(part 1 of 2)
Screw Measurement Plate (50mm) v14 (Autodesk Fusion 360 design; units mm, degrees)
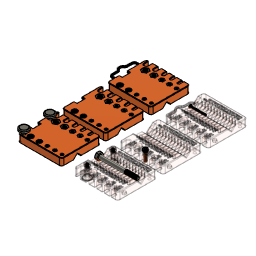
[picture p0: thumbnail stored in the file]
parameter "lengthMeasureLine" = 54 (= "( ( countMeasureCopies * 4 ) * 1 mm ) + 2 mm + 4 mm") comment "Length of measurement line"
parameter "wallMargin" = 0.2 comment "Margin for wall expansion on critical diameters"
sketch "Outline" plane through (0, 0, 0) normal (0, 0, 1) x axis (1, 0, 0)
  line L1 (-27, 10) -> (-31, 10)
  line L2 (-27, 0) -> (-27, 10)
  line L3 (-31, 0) -> (-27, 0)
  line L4 (-31, 10) -> (-31, 0)
  line L5 (27, 5) -> (-27, 5)
  line L6 (0, 5) -> (0, 0)
  line L7 (-31, -8) -> (-31, 0)
  line L8 (-27, -8) -> (-31, -8)
  line L9 (-27, 0) -> (-27, -8)
  line L10 (-27, 18) -> (-27, 10)
  line L11 (-31, 18) -> (-27, 18)
  line L12 (-31, 10) -> (-31, 18)
  line L13 (-31, 26) -> (-31, 18)
  line L14 (27, 26) -> (-31, 26)
  line L15 (27, -26) -> (27, 26)
  line L16 (-31, -26) -> (-31, -8)
  line L17 (27, -26) -> (-31, -26)
  line L18 (27, 0) -> (0, 0)
  line L19 (27, 0) -> (-27, 0)
  line L20 (27, 10) -> (-27, 10)
  point P4 (-27, 0)
  point P6 (-27, 0)
  point P7 (-27, 5)
  point P1 (0, 0)
  point P9 (0, 0)
  point P10 (0, 5)
  point P8 (27, 5)
  point P17 (27, -26)
  point P19 (27, -26)
  point P20 (0, 0)
  point P21 (27, 0)
  point P22 (27, 10)
  point P2 (-31, 10)
  point P5 (-31, 0)
  point P3 (-27, 10)
  point P14 (-31, 18)
  point P15 (-31, 26)
  point P11 (-31, -8)
  point P18 (-31, -26)
  point P16 (27, 26)
  horizontal L1
  vertical L2
  horizontal L3
  vertical L4
  coincident P4 P6
  midpoint L2 P7
  coincident P1 P9
  coincident L5 P10
  vertical L6
  horizontal L5
  midpoint L5 P10
  vertical L12
  horizontal L11
  vertical L10
  vertical L7
  vertical L9
  horizontal L8
  vertical L13
  horizontal L14
  vertical L15
  coincident P8 L15
  perpendicular L8 L16
  coincident P17 P19
  horizontal L17
  coincident P1 P20
  coincident L15 P21
  perpendicular L15 L18
  midpoint L15 P21
  coincident L15 P22
  perpendicular L15 L20
  equal L7 L12
  dimension "d142" distance P2 P5 = 10
  dimension "d143" distance P2 P3 = 4
  dimension "d144" distance P1 P6 = 27
  dimension "d148" distance P7 P8 = 54 (= "lengthMeasureLine")
  dimension "d149" distance P14 P15 = 8
  dimension "d150" distance P11 P18 = 18
  dimension "d152" distance P17 P18 = 58
  dimension "d153" distance P16 P17 = 52
  dimension "d164" distance P9 P10 = 5
  dimension "d200" distance P2 P14 = 8
extrude "Extrude1" new body sketch "Outline" profile of L2 L8 L9 L10 L11 L13 L14 L15 L16 L17 along normal blind 10
extrude "Extrude2" add sketch "Outline" profile of L1 L3 L7 L8 L9 L10 L11 L12 along normal blind 2
chamfer "Chamfer1" distance 8
extrude "Extrude3" cut sketch "Outline" profile of L2 L15 L19 L20 to an object from offset 5
chamfer "Chamfer2" distance 5
sketch "Outline, Ruler Lines" plane through (0, 0, 0) normal (0, 0, 1) x axis (1, 0, 0)
  line L1 (27, 5) -> (-27, 5)
  line L2 (-22.4874, 15.341) -> (-21, 13.8536)
  line L3 (-20.75, 5) -> (-21.25, 5)
  line L4 (-22.6642, 15.1642) -> (-21.25, 13.75)
  line L5 (-24.6642, -5.1642) -> (-23.25, -3.75)
  line L6 (-24.4874, -5.341) -> (-23, -3.8536)
  line L7 (-24.3107, -5.5178) -> (-24.6642, -5.1642)
  line L8 (-20.75, 13.9571) -> (-22.3107, 15.5178)
  line L9 (-22.75, 5) -> (-23.25, 5)
  line L10 (-22.75, -3.9571) -> (-24.3107, -5.5178)
  line L11 (-23, -3.8536) -> (-23, 5)
  line L12 (-23.25, -3.75) -> (-23.25, 5)
  line L13 (-22.75, 5) -> (-22.75, -3.9571)
  line L14 (-21.25, 13.75) -> (-21.25, 5)
  line L15 (-21, 13.8536) -> (-21, 5)
  line L16 (-20.75, 5) -> (-20.75, 13.9571)
  line L17 (27, -26) -> (27, 26)
  line L18 (27, 0) -> (0, 0)
  line L19 (0, 5) -> (0, 0)
  line L20 (-22.3107, 15.5178) -> (-22.6642, 15.1642)
  line L21 (-16.75, 5) -> (-16.75, 13.9571)
  line L22 (-17.25, 13.75) -> (-17.25, 5)
  line L23 (-18.75, 5) -> (-18.75, -3.9571)
  line L24 (-19.25, -3.75) -> (-19.25, 5)
  line L25 (-16.75, 13.9571) -> (-18.3107, 15.5178)
  line L26 (-18.3107, 15.5178) -> (-18.6642, 15.1642)
  line L27 (-18.6642, 15.1642) -> (-17.25, 13.75)
  line L28 (-16.75, 5) -> (-17.25, 5)
  line L29 (-18.75, 5) -> (-19.25, 5)
  line L30 (-18.75, -3.9571) -> (-20.3107, -5.5178)
  line L31 (-20.6642, -5.1642) -> (-19.25, -3.75)
  line L32 (-20.3107, -5.5178) -> (-20.6642, -5.1642)
  line L33 (-12.75, 5) -> (-12.75, 13.9571)
  line L34 (-13.25, 13.75) -> (-13.25, 5)
  line L35 (-14.75, 5) -> (-14.75, -3.9571)
  line L36 (-15.25, -3.75) -> (-15.25, 5)
  line L37 (-12.75, 13.9571) -> (-14.3107, 15.5178)
  line L38 (-14.3107, 15.5178) -> (-14.6642, 15.1642)
  line L39 (-14.6642, 15.1642) -> (-13.25, 13.75)
  line L40 (-12.75, 5) -> (-13.25, 5)
  line L41 (-14.75, 5) -> (-15.25, 5)
  line L42 (-14.75, -3.9571) -> (-16.3107, -5.5178)
  line L43 (-16.6642, -5.1642) -> (-15.25, -3.75)
  line L44 (-16.3107, -5.5178) -> (-16.6642, -5.1642)
  line L45 (-8.75, 5) -> (-8.75, 13.9571)
  line L46 (-9.25, 13.75) -> (-9.25, 5)
  line L47 (-10.75, 5) -> (-10.75, -3.9571)
  line L48 (-11.25, -3.75) -> (-11.25, 5)
  line L49 (-8.75, 13.9571) -> (-10.3107, 15.5178)
  line L50 (-10.3107, 15.5178) -> (-10.6642, 15.1642)
  line L51 (-10.6642, 15.1642) -> (-9.25, 13.75)
  line L52 (-8.75, 5) -> (-9.25, 5)
  line L53 (-10.75, 5) -> (-11.25, 5)
  line L54 (-10.75, -3.9571) -> (-12.3107, -5.5178)
  line L55 (-12.6642, -5.1642) -> (-11.25, -3.75)
  line L56 (-12.3107, -5.5178) -> (-12.6642, -5.1642)
  line L57 (-4.75, 5) -> (-4.75, 13.9571)
  line L58 (-5.25, 13.75) -> (-5.25, 5)
  line L59 (-6.75, 5) -> (-6.75, -3.9571)
  line L60 (-7.25, -3.75) -> (-7.25, 5)
  line L61 (-4.75, 13.9571) -> (-6.3107, 15.5178)
  line L62 (-6.3107, 15.5178) -> (-6.6642, 15.1642)
  line L63 (-6.6642, 15.1642) -> (-5.25, 13.75)
  line L64 (-4.75, 5) -> (-5.25, 5)
  line L65 (-6.75, 5) -> (-7.25, 5)
  line L66 (-6.75, -3.9571) -> (-8.3107, -5.5178)
  line L67 (-8.6642, -5.1642) -> (-7.25, -3.75)
  line L68 (-8.3107, -5.5178) -> (-8.6642, -5.1642)
  line L69 (-0.75, 5) -> (-0.75, 13.9571)
  line L70 (-1.25, 13.75) -> (-1.25, 5)
  line L71 (-2.75, 5) -> (-2.75, -3.9571)
  line L72 (-3.25, -3.75) -> (-3.25, 5)
  line L73 (-0.75, 13.9571) -> (-2.3107, 15.5178)
  line L74 (-2.3107, 15.5178) -> (-2.6642, 15.1642)
  line L75 (-2.6642, 15.1642) -> (-1.25, 13.75)
  line L76 (-0.75, 5) -> (-1.25, 5)
  line L77 (-2.75, 5) -> (-3.25, 5)
  line L78 (-2.75, -3.9571) -> (-4.3107, -5.5178)
  line L79 (-4.6642, -5.1642) -> (-3.25, -3.75)
  line L80 (-4.3107, -5.5178) -> (-4.6642, -5.1642)
  line L81 (3.25, 5) -> (3.25, 13.9571)
  line L82 (2.75, 13.75) -> (2.75, 5)
  line L83 (1.25, 5) -> (1.25, -3.9571)
  line L84 (0.75, -3.75) -> (0.75, 5)
  line L85 (3.25, 13.9571) -> (1.6893, 15.5178)
  line L86 (1.6893, 15.5178) -> (1.3358, 15.1642)
  line L87 (1.3358, 15.1642) -> (2.75, 13.75)
  line L88 (3.25, 5) -> (2.75, 5)
  line L89 (1.25, 5) -> (0.75, 5)
  line L90 (1.25, -3.9571) -> (-0.3107, -5.5178)
  line L91 (-0.6642, -5.1642) -> (0.75, -3.75)
  line L92 (-0.3107, -5.5178) -> (-0.6642, -5.1642)
  line L93 (7.25, 5) -> (7.25, 13.9571)
  line L94 (6.75, 13.75) -> (6.75, 5)
  line L95 (5.25, 5) -> (5.25, -3.9571)
  line L96 (4.75, -3.75) -> (4.75, 5)
  line L97 (7.25, 13.9571) -> (5.6893, 15.5178)
  line L98 (5.6893, 15.5178) -> (5.3358, 15.1642)
  line L99 (5.3358, 15.1642) -> (6.75, 13.75)
  line L100 (7.25, 5) -> (6.75, 5)
  line L101 (5.25, 5) -> (4.75, 5)
  line L102 (5.25, -3.9571) -> (3.6893, -5.5178)
  line L103 (3.3358, -5.1642) -> (4.75, -3.75)
  line L104 (3.6893, -5.5178) -> (3.3358, -5.1642)
  line L105 (11.25, 5) -> (11.25, 13.9571)
  line L106 (10.75, 13.75) -> (10.75, 5)
  line L107 (9.25, 5) -> (9.25, -3.9571)
  line L108 (8.75, -3.75) -> (8.75, 5)
  line L109 (11.25, 13.9571) -> (9.6893, 15.5178)
  line L110 (9.6893, 15.5178) -> (9.3358, 15.1642)
  line L111 (9.3358, 15.1642) -> (10.75, 13.75)
  line L112 (11.25, 5) -> (10.75, 5)
  line L113 (9.25, 5) -> (8.75, 5)
  line L114 (9.25, -3.9571) -> (7.6893, -5.5178)
  line L115 (7.3358, -5.1642) -> (8.75, -3.75)
  line L116 (7.6893, -5.5178) -> (7.3358, -5.1642)
  line L117 (15.25, 5) -> (15.25, 13.9571)
  line L118 (14.75, 13.75) -> (14.75, 5)
  line L119 (13.25, 5) -> (13.25, -3.9571)
  line L120 (12.75, -3.75) -> (12.75, 5)
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  point P13 (-24.4874, -5.341)
  point P3 (-23, 5)
  point P4 (-21, 5)
  point P27 (0, 5)
  point P17 (27, 5)
  point P19 (-22.4874, 15.341)
  point P8 (-24.6642, -5.1642)
  point P21 (-24.3107, -5.5178)
  point P7 (-23.25, -3.75)
  point P9 (-23.25, 5)
  point P16 (-27, 5)
  horizontal L1
  vertical L13
  vertical L11
  vertical L12
  parallel L6 L10
  parallel L5 L6
  midpoint P13 L7
  perpendicular L5 L7
  perpendicular L9 L13
  midpoint P3 L9
  equal L7 L9
  midpoint P4 L3
  vertical L15
  vertical L14
  vertical L16
  horizontal L3
  parallel L2 L8
  coincident P3 L1
  equal L3 L9
  equal L12 L14
  equal L4 L5
  coincident P4 L1
  parallel L2 L4
  coincident L1 P27
  coincident P17 L17
  midpoint L1 P27
  midpoint P19 L20
  equal L3 L20
  perpendicular L4 L20
  dimension "d168" angle L6 L11 = 135
  dimension "d169" distance P8 P21 = 0.5
  dimension "d170" distance P7 P9 = 8.75
  dimension "d171" distance P7 P8 = 2
  dimension "d172" distance P3 P16 = 4
  dimension "d173" distance P4 P16 = 6
  dimension "d174" angle L2 L15 = 135
  dimension "d180" R-Pattern1-uDistance = 4
  dimension "d181" R-Pattern1-vDistance = 0
extrude "Extrude4" cut sketch "Outline, Ruler Lines" to an object from offset 5
sketch "Outline, Pockets (M5)" plane through (0, 0, 0) normal (0, 0, 1) x axis (1, 0, 0)
  line L1 (-31, -26) -> (-31, -8)
  line L2 (27, -26) -> (27, 26)
  line L3 (27, -26) -> (-31, -26)
  line L4 (18.7, -20) -> (16.7, -20)
  line L5 (-3.8, -20) -> (-11.3, -20)
  line L6 (18.7, -23) -> (-27.8, -23)
  line L7 (16.7, -20) -> (9.2, -20)
  line L8 (-15.3, -20) -> (-22.8, -20)
  line L9 (-11.3, -20) -> (-15.3, -20)
  line L10 (-11.3, -20) -> (-11.3, -26)
  line L11 (-15.3, -20) -> (-15.3, -26)
  line L12 (9.2, -20) -> (6.7, -20)
  line L13 (-22.8, -20) -> (-22.8, -26)
  line L14 (-22.8, -20) -> (-27.8, -20)
  line L15 (16.7, -20) -> (16.7, -26)
  line L16 (-3.8, -20) -> (-3.8, -26)
  line L17 (-27.8, -20) -> (-27.8, -26)
  line L18 (-0.8, -20) -> (-0.8, -26)
  line L19 (-0.8, -20) -> (-3.8, -20)
  line L20 (18.7, -20) -> (18.7, -26)
  line L21 (6.7, -20) -> (6.7, -26)
  line L22 (6.7, -20) -> (-0.8, -20)
  line L23 (9.2, -20) -> (9.2, -26)
  arc A1 centre (7.95, -20) radius 1.25 clockwise from (6.7, -20) to (9.2, -20)
  arc A2 centre (-13.3, -20) radius 2 clockwise from (-15.3, -20) to (-11.3, -20)
  arc A3 centre (-25.3, -20) radius 2.5 clockwise from (-27.8, -20) to (-22.8, -20)
  arc A4 centre (17.7, -20) radius 1 clockwise from (16.7, -20) to (18.7, -20)
  arc A5 centre (-2.3, -20) radius 1.5 clockwise from (-3.8, -20) to (-0.8, -20)
  point P32 (-27.8, -20)
  point P45 (-27.8, -20)
  point P15 (-22.8, -20)
  point P44 (-22.8, -20)
  point P26 (-25.3, -20)
  point P8 (-15.3, -20)
  point P9 (-15.3, -20)
  point P34 (-11.3, -20)
  point P43 (-11.3, -20)
  point P16 (-13.3, -20)
  point P12 (-3.8, -20)
  point P19 (-3.8, -20)
  point P23 (-0.8, -20)
  point P33 (-0.8, -20)
  point P24 (-2.3, -20)
  point P25 (9.2, -20)
  point P35 (9.2, -20)
  point P27 (6.7, -20)
  point P38 (6.7, -20)
  point P22 (7.95, -20)
  point P29 (16.7, -20)
  point P31 (16.7, -20)
  point P40 (16.7, -20)
  point P10 (18.7, -20)
  point P21 (18.7, -20)
  point P28 (17.7, -20)
  point P13 (-27.8, -23)
  point P11 (18.7, -23)
  point P14 (-27.8, -26)
  point P30 (-15.3, -26)
  point P17 (-11.3, -26)
  point P37 (-3.8, -26)
  point P20 (-0.8, -26)
  point P36 (6.7, -26)
  point P39 (9.2, -26)
  point P41 (16.7, -26)
  point P42 (18.7, -26)
  point P18 (-22.8, -26)
  point P3 (-31, -26)
  horizontal L14
  coincident P32 P45
  coincident P15 P44
  coincident P26 L14
  horizontal L9
  horizontal L8
  coincident P8 P9
  coincident P34 P43
  vertical L10
  vertical L11
  vertical L13
  vertical L17
  midpoint P16 L9
  horizontal L5
  coincident P12 P19
  vertical L16
  horizontal L19
  coincident P23 P33
  midpoint P24 L19
  vertical L18
  horizontal L22
  horizontal L12
  coincident P25 P35
  coincident P27 P38
  vertical L21
  vertical L23
  midpoint P22 L12
  coincident P29 P31
  horizontal L7
  horizontal L4
  coincident P31 P40
  coincident P10 P21
  vertical L15
  vertical L20
  midpoint P28 L4
  midpoint P13 L17
  midpoint P11 L20
  coincident L3 P14
  coincident L3 P30
  coincident L3 P17
  coincident L3 P37
  coincident L3 P20
  coincident L3 P36
  coincident L3 P39
  coincident L3 P41
  coincident L3 P42
  coincident L3 P18
  dimension "d185" distance P14 P18 = 5
  dimension "d186" distance P18 P30 = 7.5
  dimension "d187" distance P17 P30 = 4
  dimension "d188" distance P17 P37 = 7.5
  dimension "d189" distance P20 P37 = 3
  dimension "d190" distance P20 P36 = 7.5
  dimension "d191" distance P36 P39 = 2.5
  dimension "d192" distance P39 P41 = 7.5
  dimension "d193" distance P41 P42 = 2
  dimension "d194" distance P3 P14 = 3.2
  dimension "d195" distance P14 P32 = 6
extrude "Extrude5" cut sketch "Outline, Pockets (M5)" profile of L3 L10 A1 L11 A2 L13 L15 L16 L17 L18 L20 L21 A3 A4 L23 A5 to an object
base_feature "Base Feature1" bodies "Nut, M2 (91828A111) v1"
base_feature "Base Feature1" bodies "Nut, M2.5 (91828A113) v1"
base_feature "Base Feature1" bodies "Nut, M3 (91828A211) v1 (1)"
base_feature "Base Feature1" bodies "Nut, M4 (91828A231) v1"
base_feature "Base Feature1" bodies "Nut, M5 (91828A241) v1"
position "Position3"
base_feature "Base Feature1" bodies "Insert, M3, Short (CNC Kitchen) v2"
base_feature "Base Feature1" bodies "Insert, M4, Short (CNC Kitchen) v2"
base_feature "Base Feature1" bodies "Insert, M5, Short (CNC Kitchen) v2"
base_feature "Base Feature1" bodies "Insert, M2 [3.3x2.5] (McMaster 94459A110) v2"
base_feature "Base Feature1" bodies "Insert, M2.5 [4.1x5.9] (McMaster 94459A439) v3"
sketch "Outline, Nuts & Inserts" plane through (0, 0, 0) normal (0, 0, 1) x axis (1, 0, 0)
  line L1 (27, -26) -> (-31, -26)
  line L2 (-31, -26) -> (-31, -8)
  line L3 (27, 26) -> (-31, 26)
  line L4 (27, -26) -> (27, 26)
  line L5 (27, 5) -> (-27, 5)
  line L6 (-24.6642, -5.1642) -> (-23.25, -3.75)
  line L7 (23.25, 13.9571) -> (21.6893, 15.5178)
  line L8 (23.25, -5.5178) -> (-24.6642, -5.5178)
  line L9 (23.25, 15.5178) -> (23.25, -5.5178)
  line L10 (-24.6642, 15.5178) -> (23.25, 15.5178)
  line L11 (-24.6642, -5.5178) -> (-24.6642, 15.5178)
  line L12 (-22.75, -3.9571) -> (-24.3107, -5.5178)
  line L13 (21.3358, 15.1642) -> (22.75, 13.75)
  line L14 (-25.3, -5.5178) -> (-25.3, -20)
  line L15 (-24.6642, -5.5178) -> (-25.3, -5.5178)
  line L16 (-13.3, -5.5178) -> (-13.3, -20)
  line L17 (-2.3, -5.5178) -> (-2.3, -20)
  line L18 (7.95, -5.5178) -> (7.95, -20)
  line L19 (17.7, -5.5178) -> (17.7, -20)
  line L20 (-13.3, -12.7589) -> (-25.3, -12.7589)
  line L21 (-2.3, -12.7589) -> (-13.3, -12.7589)
  line L22 (-2.3, -12.7589) -> (7.95, -12.7589)
  line L23 (17.7, -12.7589) -> (7.95, -12.7589)
  line L24 (27, -12.7589) -> (17.7, -12.7589)
  line L25 (27, -26) -> (27, 26)
  line L26 (12.825, -5.5178) -> (12.825, -12.7589)
  line L27 (2.825, -5.5178) -> (2.825, -12.7589)
  line L28 (-7.8, -5.5178) -> (-7.8, -12.7589)
  line L29 (-19.3, -5.5178) -> (-19.3, -12.7589)
  line L30 (22.35, -5.5178) -> (22.35, -12.7589)
  line L31 (-19.3, -17.4932) -> (-23.4, -15.126)
  line L32 (-15.2, -15.126) -> (-19.3, -17.4932)
  line L33 (-15.2, -10.3917) -> (-15.2, -15.126)
  line L34 (-19.3, -8.0246) -> (-15.2, -10.3917)
  line L35 (-23.4, -10.3917) -> (-19.3, -8.0246)
  line L36 (-23.4, -15.126) -> (-23.4, -10.3917)
  line L37 (-7.8, -16.9158) -> (-11.4, -14.8373)
  line L38 (-4.2, -14.8373) -> (-7.8, -16.9158)
  line L39 (-4.2, -10.6804) -> (-4.2, -14.8373)
  line L40 (-7.8, -8.602) -> (-4.2, -10.6804)
  line L41 (-11.4, -10.6804) -> (-7.8, -8.602)
  line L42 (-11.4, -14.8373) -> (-11.4, -10.6804)
  line L43 (2.825, -16.0498) -> (-0.025, -14.4043)
  line L44 (5.675, -14.4043) -> (2.825, -16.0498)
  line L45 (5.675, -11.1134) -> (5.675, -14.4043)
  line L46 (2.825, -9.468) -> (5.675, -11.1134)
  line L47 (-0.025, -11.1134) -> (2.825, -9.468)
  line L48 (-0.025, -14.4043) -> (-0.025, -11.1134)
  line L49 (12.825, -15.7611) -> (10.225, -14.26)
  line L50 (15.425, -14.26) -> (12.825, -15.7611)
  line L51 (15.425, -11.2578) -> (15.425, -14.26)
  line L52 (12.825, -9.7567) -> (15.425, -11.2578)
  line L53 (10.225, -11.2578) -> (12.825, -9.7567)
  line L54 (10.225, -14.26) -> (10.225, -11.2578)
  line L55 (22.35, -15.1838) -> (20.25, -13.9713)
  line L56 (24.45, -13.9713) -> (22.35, -15.1838)
  line L57 (24.45, -11.5464) -> (24.45, -13.9713)
  line L58 (22.35, -10.334) -> (24.45, -11.5464)
  line L59 (20.25, -11.5464) -> (22.35, -10.334)
  line L60 (20.25, -13.9713) -> (20.25, -11.5464)
  line L61 (-25.3, 26) -> (-25.3, -5.5178)
  line L62 (-24.6642, 26) -> (-24.6642, 15.5178)
  line L63 (-19.3, 26) -> (-19.3, 15.5178)
  line L64 (-7.8, 26) -> (-7.8, 15.5178)
  line L65 (2.825, 26) -> (2.825, 15.5178)
  line L66 (12.825, 26) -> (12.825, 15.5178)
  line L67 (22.35, 26) -> (22.35, 15.5178)
  line L68 (22.35, 20.6589) -> (-24.6642, 20.6589)
  line L69 (-25.3, 20.7589) -> (-24.6642, 20.7589)
  arc A1 centre (-25.3, -20) radius 2.5 clockwise from (-27.8, -20) to (-22.8, -20)
  arc A2 centre (-13.3, -20) radius 2 clockwise from (-15.3, -20) to (-11.3, -20)
  arc A3 centre (-2.3, -20) radius 1.5 clockwise from (-3.8, -20) to (-0.8, -20)
  arc A4 centre (7.95, -20) radius 1.25 clockwise from (6.7, -20) to (9.2, -20)
  arc A5 centre (17.7, -20) radius 1 clockwise from (16.7, -20) to (18.7, -20)
  circle C1 centre (-19.3, 20.6589) radius 3.3
  circle C2 centre (-7.8, 20.6589) radius 2.9
  circle C3 centre (2.825, 20.6589) radius 2.1
  circle C4 centre (12.825, 20.6589) radius 2.15
  circle C5 centre (22.35, 20.6589) radius 1.75
  point P39 (-24.3107, -5.5178)
  point P40 (-24.6642, -5.1642)
  point P41 (21.6893, 15.5178)
  point P42 (23.25, 13.9571)
  point P18 (-25.3, -20)
  point P43 (-25.3, -20)
  point P21 (-13.3, -20)
  point P45 (-13.3, -20)
  point P46 (-13.3, -5.5178)
  point P24 (-2.3, -20)
  point P47 (-2.3, -20)
  point P48 (-2.3, -5.5178)
  point P27 (7.95, -20)
  point P49 (7.95, -20)
  point P50 (7.95, -5.5178)
  point P30 (17.7, -20)
  point P51 (17.7, -20)
  point P52 (17.7, -5.5178)
  point P53 (-25.3, -12.7589)
  point P54 (-13.3, -12.7589)
  point P55 (-2.3, -12.7589)
  point P56 (7.95, -12.7589)
  point P57 (17.7, -12.7589)
  point P58 (27, -12.7589)
  point P61 (12.825, -12.7589)
  point P62 (12.825, -5.5178)
  point P63 (2.825, -12.7589)
  point P64 (2.825, -5.5178)
  point P65 (-7.8, -12.7589)
  point P66 (-7.8, -5.5178)
  point P67 (-19.3, -12.7589)
  point P68 (-19.3, -5.5178)
  point P69 (22.35, -12.7589)
  point P70 (22.35, -5.5178)
  point P77 (-19.3, -12.7589)
  point P84 (-7.8, -12.7589)
  point P91 (2.825, -12.7589)
  point P98 (12.825, -12.7589)
  point P105 (22.35, -12.7589)
  point P106 (-25.3, 26)
  point P107 (-24.6642, 26)
  point P108 (-19.3, 15.5178)
  point P110 (-7.8, 15.5178)
  point P111 (-7.8, 26)
  point P112 (2.825, 15.5178)
  point P113 (2.825, 26)
  point P114 (12.825, 15.5178)
  point P115 (12.825, 26)
  point P116 (22.35, 15.5178)
  point P117 (22.35, 26)
  point P109 (-19.3, 26)
  point P119 (22.35, 20.6589)
  point P124 (22.35, 20.6589)
  point P118 (-24.6642, 20.6589)
  point P120 (-19.3, 20.6589)
  point P121 (-7.8, 20.6589)
  point P122 (2.825, 20.6589)
  point P123 (12.825, 20.6589)
  point P125 (-24.6642, 20.7589)
  point P126 (-25.3, 20.7589)
  horizontal L8
  vertical L9
  horizontal L10
  vertical L11
  coincident L8 P39
  coincident L11 P40
  coincident L10 P41
  coincident L9 P42
  coincident P18 P43
  perpendicular L8 L14
  perpendicular L11 L15
  coincident P21 P45
  coincident L8 P46
  perpendicular L8 L16
  coincident P24 P47
  coincident L8 P48
  perpendicular L8 L17
  coincident P27 P49
  coincident L8 P50
  perpendicular L8 L18
  coincident P30 P51
  coincident L8 P52
  perpendicular L8 L19
  midpoint L14 P53
  midpoint L16 P54
  midpoint L17 P55
  midpoint L18 P56
  midpoint L19 P57
  perpendicular L4 L24
  coincident P58 L25
  midpoint L23 P61
  coincident L8 P62
  perpendicular L8 L26
  midpoint L22 P63
  coincident L8 P64
  perpendicular L8 L27
  midpoint L21 P65
  coincident L8 P66
  perpendicular L8 L28
  midpoint L20 P67
  coincident L8 P68
  perpendicular L8 L29
  midpoint L24 P69
  coincident L8 P70
  perpendicular L8 L30
  coincident P67 P77
  coincident P65 P84
  coincident P63 P91
  coincident P61 P98
  coincident P69 P105
  vertical L33
  vertical L42
  vertical L48
  vertical L54
  vertical L60
  coincident L3 P106
  perpendicular L3 L61
  coincident L3 P107
  perpendicular L3 L62
  coincident L10 P108
  perpendicular L10 L63
  coincident L10 P110
  coincident L3 P111
  perpendicular L3 L64
  collinear L28 L64
  collinear L29 L63
  coincident L10 P112
  coincident L3 P113
  perpendicular L3 L65
  coincident L10 P114
  coincident L3 P115
  perpendicular L3 L66
  coincident L10 P116
  coincident L3 P117
  perpendicular L3 L67
  collinear L27 L65
  collinear L26 L66
  collinear L30 L67
  coincident L3 P109
  coincident P119 P124
  horizontal L68
  coincident L62 P118
  coincident L67 P119
  coincident L68 P120
  coincident L64 P121
  coincident L68 P121
  coincident L68 P122
  coincident L68 P123
  midpoint L62 P125
  coincident L61 P126
  perpendicular L61 L69
  coincident L63 P120
  coincident L65 P122
  coincident L66 P123
  dimension "diaM5Nut" distance L33 L36 = 8.2 (= "8 mm + wallMargin")
  dimension "diaM4Nut" distance L39 L42 = 7.2 (= "7 mm + wallMargin")
  dimension "diaM3Nut" distance L45 L48 = 5.7 (= "5.5 mm + wallMargin")
  dimension "diaM25Nut" distance L51 L54 = 5.2 (= "5 mm + wallMargin")
  dimension "diaM2Nut" distance L57 L60 = 4.2 (= "4 mm + wallMargin")
  dimension "diaM5Insert" diameter C1 = 6.6 (= "6.4 mm + wallMargin")
  dimension "diaM4Insert" diameter C2 = 5.8 (= "5.6 mm + wallMargin")
  dimension "diaM3Insert" diameter C3 = 4.2 (= "4 mm + wallMargin")
  dimension "diaM25Insert" diameter C4 = 4.3 (= "4.1 mm + wallMargin")
  dimension "diaM2Insert" diameter C5 = 3.5 (= "3.3 mm + wallMargin")
  dimension "d467" distance L68 P126 = 0.1
extrude "Extrude14" cut sketch "Outline, Nuts & Inserts" profile of L31 L32 L33 L34 L35 L36 along normal blind 4.11
extrude "Extrude15" cut sketch "Outline, Nuts & Inserts" profile of L37 L38 L39 L40 L41 L42 along normal blind 3.3
extrude "Extrude16" cut sketch "Outline, Nuts & Inserts" profile of L43 L44 L45 L46 L47 L48 along normal blind 2.5
extrude "Extrude17" cut sketch "Outline, Nuts & Inserts" profile of L49 L50 L51 L52 L53 L54 along normal blind 2.1
extrude "Extrude18" cut sketch "Outline, Nuts & Inserts" profile of L55 L56 L57 L58 L59 L60 along normal blind 1.7
extrude "Extrude19" cut sketch "Outline, Nuts & Inserts" profile of C1 along normal blind 6.8
extrude "Extrude20" cut sketch "Outline, Nuts & Inserts" profile of C2 along normal blind 5
extrude "Extrude21" cut sketch "Outline, Nuts & Inserts" profile of C3 along normal blind 6.7
extrude "Extrude22" cut sketch "Outline, Nuts & Inserts" profile of C4 along normal blind 6.9
extrude "Extrude23" cut sketch "Outline, Nuts & Inserts" profile of C5 along normal blind 3.5
joint "Assemble1" alignAngle 0 alignOffsetX 0 alignOffsetY 0 alignOffsetZ 0
joint "Assemble2" alignAngle 0 alignOffsetX 0 alignOffsetY 0 alignOffsetZ 0
joint "Assemble3" alignAngle 0 alignOffsetX 0 alignOffsetY 0 alignOffsetZ 0
joint "Assemble4" alignAngle 0 alignOffsetX 0 alignOffsetY 0 alignOffsetZ 0
joint "Assemble5" alignAngle 0 alignOffsetX 0 alignOffsetY 0 alignOffsetZ 0
sketch "Labels, Bottom (Original)" plane through (0, 0, 0) normal (0, 0, 1) x axis (1, 0, 0)
  dimension "d482" = 1
  dimension "d512" = 3
  dimension "d514" = 3
  dimension "d516" = 3
  dimension "d517" = 2
  dimension "d520" = 3
  dimension "d521" = 3
  dimension "d522" = 3
  dimension "d523" = 3
  dimension "d524" = 3
  dimension "d525" = 3
  dimension "d526" = 3
  dimension "d527" = 3
  dimension "d529" = 3
  dimension "d530" = 2
  dimension "d531" = 3
  dimension "d532" = 2
  dimension "d533" = 3
  dimension "d534" = 2
  dimension "d535" = 3
  dimension "d536" = 2
  dimension "d537" = 3
  dimension "d539" = 2
  dimension "d542" = 0.5
  dimension "d551" = 2
  dimension "d552" = 3
  dimension "d553" = 3
  dimension "d554" = 2
  dimension "d555" = 3
  dimension "d556" = 2
  dimension "d557" = 3
  dimension "d558" = 2
sketch "Labels, Bottom" plane through (0, 0, 0) normal (0, 0, 1) x axis (1, 0, 0)
  line L1 (-22.85, 14.0846) -> (-22.85, 16.5178)
  line L2 (-22.2872, 14.0846) -> (-22.85, 14.0846)
  curve K1 (-21.6672, 14.6146) -> (-22.2872, 14.0846)
  curve K2 (-20.7647, 15.0219) -> (-21.6672, 14.6146)
  curve K3 (-19.85, 15.1815) -> (-20.7647, 15.0219)
  line L3 (-19.85, 16.0123) -> (-19.85, 15.1815)
  curve K4 (-21.0819, 15.7033) -> (-19.85, 16.0123)
  curve K5 (-22.146, 15.0362) -> (-21.0819, 15.7033)
  line L4 (-22.146, 16.5178) -> (-22.146, 15.0362)
  line L5 (-22.85, 16.5178) -> (-22.146, 16.5178)
  line L6 (-20.6849, 12.7647) -> (-20.6849, 13.6549)
  line L7 (-19.85, 12.7647) -> (-20.6849, 12.7647)
  line L8 (-19.85, 13.6549) -> (-19.85, 12.7647)
  line L9 (-20.6849, 13.6549) -> (-19.85, 13.6549)
  line L10 (-19.85, 10.4523) -> (-22.9012, 10.4523)
  line L11 (-19.85, 11.2954) -> (-19.85, 10.4523)
  line L12 (-21.8493, 11.2954) -> (-19.85, 11.2954)
  curve K6 (-21.5976, 11.6914) -> (-21.8493, 11.2954)
  curve K7 (-21.4134, 12.1712) -> (-21.5976, 11.6914)
  line L13 (-22.0969, 12.1712) -> (-21.4134, 12.1712)
  curve K8 (-22.4264, 11.5103) -> (-22.0969, 12.1712)
  curve K9 (-22.9012, 11.1419) -> (-22.4264, 11.5103)
  line L14 (-22.9012, 10.4523) -> (-22.9012, 11.1419)
  curve K10 (-21.6958, -1.0969) -> (-21.4626, -1.3834)
  curve K11 (-22.101, -0.9741) -> (-21.6958, -1.0969)
  curve K12 (-22.717, -1.3282) -> (-22.101, -0.9741)
  curve K13 (-22.9012, -2.0587) -> (-22.717, -1.3282)
  curve K14 (-22.672, -2.9479) -> (-22.9012, -2.0587)
  curve K15 (-22.0949, -3.2354) -> (-22.672, -2.9479)
  curve K16 (-21.7163, -3.1208) -> (-22.0949, -3.2354)
  curve K17 (-21.4626, -2.8507) -> (-21.7163, -3.1208)
  curve K18 (-21.1535, -3.2139) -> (-21.4626, -2.8507)
  curve K19 (-20.7279, -3.3336) -> (-21.1535, -3.2139)
  curve K20 (-20.3074, -3.2303) -> (-20.7279, -3.3336)
  curve K21 (-20.0055, -2.9765) -> (-20.3074, -3.2303)
  curve K22 (-19.849, -2.602) -> (-20.0055, -2.9765)
  curve K23 (-19.7988, -2.1242) -> (-19.849, -2.602)
  curve K24 (-19.9114, -1.3957) -> (-19.7988, -2.1242)
  curve K25 (-20.2429, -1.013) -> (-19.9114, -1.3957)
  curve K26 (-20.732, -0.882) -> (-20.2429, -1.013)
  curve K27 (-21.1791, -1.0048) -> (-20.732, -0.882)
  curve K28 (-21.4626, -1.3834) -> (-21.1791, -1.0048)
  curve K29 (-21.8012, -1.8551) -> (-22.0519, -1.7579)
  curve K30 (-21.7061, -2.114) -> (-21.8012, -1.8551)
  curve K31 (-21.8002, -2.3493) -> (-21.7061, -2.114)
  curve K32 (-22.0437, -2.4414) -> (-21.8002, -2.3493)
  curve K33 (-22.2965, -2.3452) -> (-22.0437, -2.4414)
  curve K34 (-22.3937, -2.0996) -> (-22.2965, -2.3452)
  curve K35 (-22.2985, -1.8531) -> (-22.3937, -2.0996)
  curve K36 (-22.0519, -1.7579) -> (-22.2985, -1.8531)
  curve K37 (-20.4363, -1.8336) -> (-20.7606, -1.7129)
  curve K38 (-20.3104, -2.1099) -> (-20.4363, -1.8336)
  curve K39 (-20.4383, -2.378) -> (-20.3104, -2.1099)
  curve K40 (-20.7627, -2.4966) -> (-20.4383, -2.378)
  curve K41 (-21.0881, -2.3769) -> (-20.7627, -2.4966)
  curve K42 (-21.2149, -2.0996) -> (-21.0881, -2.3769)
  curve K43 (-21.0922, -1.8285) -> (-21.2149, -2.0996)
  curve K44 (-20.7606, -1.7129) -> (-21.0922, -1.8285)
  line L15 (-20.6849, -4.6494) -> (-20.6849, -3.7593)
  line L16 (-19.85, -4.6494) -> (-20.6849, -4.6494)
  line L17 (-19.85, -3.7593) -> (-19.85, -4.6494)
  line L18 (-20.6849, -3.7593) -> (-19.85, -3.7593)
  curve K45 (-22.5594, -5.381) -> (-21.3623, -5.073)
  curve K46 (-22.9012, -6.3193) -> (-22.5594, -5.381)
  curve K47 (-22.8265, -6.8166) -> (-22.9012, -6.3193)
  curve K48 (-22.6321, -7.1338) -> (-22.8265, -6.8166)
  curve K49 (-22.3804, -7.3271) -> (-22.6321, -7.1338)
  curve K50 (-22.0724, -7.4407) -> (-22.3804, -7.3271)
  curve K51 (-21.3725, -7.5246) -> (-22.0724, -7.4407)
  curve K52 (-20.1774, -7.2483) -> (-21.3725, -7.5246)
  curve K53 (-19.7988, -6.2968) -> (-20.1774, -7.2483)
  curve K54 (-19.9196, -5.6849) -> (-19.7988, -6.2968)
  curve K55 (-20.2736, -5.3022) -> (-19.9196, -5.6849)
  curve K56 (-20.7269, -5.1334) -> (-20.2736, -5.3022)
  curve K57 (-21.3623, -5.073) -> (-20.7269, -5.1334)
  curve K58 (-20.5775, -6.0011) -> (-21.3602, -5.8998)
  curve K59 (-20.3677, -6.2947) -> (-20.5775, -6.0011)
  curve K60 (-20.4568, -6.5147) -> (-20.3677, -6.2947)
  curve K61 (-20.7381, -6.6518) -> (-20.4568, -6.5147)
  curve K62 (-21.3377, -6.6958) -> (-20.7381, -6.6518)
  curve K63 (-22.1409, -6.5945) -> (-21.3377, -6.6958)
  curve K64 (-22.3466, -6.2906) -> (-22.1409, -6.5945)
  curve K65 (-22.1368, -5.9919) -> (-22.3466, -6.2906)
  curve K66 (-21.3602, -5.8998) -> (-22.1368, -5.9919)
  line L19 (-22.9523, 2.5851) -> (-22.6156, 2.94)
  line L20 (-22.6229, 2.2761) -> (-22.9523, 2.5851)
  line L21 (-22.2874, 2.6303) -> (-22.6229, 2.2761)
  curve K67 (-21.8751, 2.4603) -> (-22.2874, 2.6303)
  curve K68 (-21.3542, 2.3988) -> (-21.8751, 2.4603)
  curve K69 (-20.4895, 2.588) -> (-21.3542, 2.3988)
  curve K70 (-19.9748, 3.1096) -> (-20.4895, 2.588)
  curve K71 (-19.7988, 3.9472) -> (-19.9748, 3.1096)
  curve K72 (-19.8905, 4.5915) -> (-19.7988, 3.9472)
  curve K73 (-20.0841, 4.9556) -> (-19.8905, 4.5915)
  line L22 (-19.7436, 5.3149) -> (-20.0841, 4.9556)
  line L23 (-20.069, 5.6239) -> (-19.7436, 5.3149)
  line L24 (-20.4117, 5.2628) -> (-20.069, 5.6239)
  curve K74 (-21.3411, 5.5073) -> (-20.4117, 5.2628)
  curve K75 (-22.4907, 5.0989) -> (-21.3411, 5.5073)
  curve K76 (-22.9012, 3.9637) -> (-22.4907, 5.0989)
  curve K77 (-22.6156, 2.94) -> (-22.9012, 3.9637)
  curve K78 (-22.1992, 3.9596) -> (-22.0486, 3.5375)
  curve K79 (-22.0015, 4.4102) -> (-22.1992, 3.9596)
  curve K80 (-21.3593, 4.5803) -> (-22.0015, 4.4102)
  curve K81 (-21.0786, 4.5598) -> (-21.3593, 4.5803)
  line L25 (-22.0486, 3.5375) -> (-21.0786, 4.5598)
  line L26 (-20.6416, 4.3671) -> (-21.6128, 3.3422)
  curve K82 (-20.4926, 3.9519) -> (-20.6416, 4.3671)
  curve K83 (-20.6851, 3.4905) -> (-20.4926, 3.9519)
  curve K84 (-21.3527, 3.3259) -> (-20.6851, 3.4905)
  curve K85 (-21.6128, 3.3422) -> (-21.3527, 3.3259)
  line L27 (-15.8661, 5.7488) -> (-15.8661, 2.1673)
  line L28 (-18.9239, 3.9503) -> (-15.8661, 5.7488)
  line L29 (-15.8661, 2.1673) -> (-18.9239, 3.9503)
  line L30 (-16.2752, 5.0886) -> (-18.1998, 3.9508)
  line L31 (-16.2752, 2.8273) -> (-16.2752, 5.0886)
  line L32 (-18.1998, 3.9508) -> (-16.2752, 2.8273)
  line L33 (-18.25, 14.9502) -> (-18.25, 16.2695)
  line L34 (-17.8066, 14.9502) -> (-18.25, 14.9502)
  line L35 (-17.8066, 15.8438) -> (-17.8066, 14.9502)
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extrude "Extrude25" cut sketch "Labels, Bottom" along normal blind 0.4
fillet "Fillet2" radius 3
fillet "Fillet1" radius 0.75
chamfer "Chamfer3" distance 0.6
sketch "Big Plane (Horizontal)" plane through (0, 0, 0) normal (0, 0, 1) x axis (1, 0, 0)
  line L1 (250, 250) -> (-250, 250)
  line L2 (250, -250) -> (250, 250)
  line L3 (-250, -250) -> (250, -250)
  line L4 (-250, 250) -> (-250, -250)
  line L5 (0, 22.5) -> (0, 1.75)
  line L6 (22.5, 0) -> (1.75, 0)
  point P2 (-250, 250)
  point P3 (250, 250)
  point P5 (-250, -250)
  horizontal L1
  vertical L2
  horizontal L3
  vertical L4
  symmetric L2 L4 L5
  symmetric L1 L3 L6
  dimension "d462" distance P2 P3 = 500
  dimension "d463" distance P2 P5 = 500
copy_paste_bodies "CopyPasteBodies9"
move "Move10"
sketch "Labels, Pockets (M5, Original)" plane through (0, 0, 10) normal (0, 0, 1) x axis (-1, 0, 0)
  line L1 (-21.25, 0) -> (-26.25, 0)
  line L2 (-21.25, 3.9571) -> (-21.25, 0)
  line L3 (-19.6893, 5.5178) -> (-21.25, 3.9571)
  line L4 (-19.3358, 5.1642) -> (-19.6893, 5.5178)
  line L5 (-20.75, 3.75) -> (-19.3358, 5.1642)
  line L6 (-20.75, 0) -> (-20.75, 3.75)
  line L7 (-17.25, 0) -> (-20.75, 0)
  line L8 (-17.25, 3.9571) -> (-17.25, 0)
  line L9 (-15.6893, 5.5178) -> (-17.25, 3.9571)
  line L10 (-15.3358, 5.1642) -> (-15.6893, 5.5178)
  line L11 (-16.75, 3.75) -> (-15.3358, 5.1642)
  line L12 (-16.75, 0) -> (-16.75, 3.75)
  line L13 (-13.25, 0) -> (-16.75, 0)
  line L14 (-13.25, 3.9571) -> (-13.25, 0)
  line L15 (-11.6893, 5.5178) -> (-13.25, 3.9571)
  line L16 (-11.3358, 5.1642) -> (-11.6893, 5.5178)
  line L17 (-12.75, 3.75) -> (-11.3358, 5.1642)
  line L18 (-12.75, 0) -> (-12.75, 3.75)
  line L19 (-9.25, 0) -> (-12.75, 0)
  line L20 (-9.25, 3.9571) -> (-9.25, 0)
  line L21 (-7.6893, 5.5178) -> (-9.25, 3.9571)
  line L22 (-7.3358, 5.1642) -> (-7.6893, 5.5178)
  line L23 (-8.75, 3.75) -> (-7.3358, 5.1642)
  line L24 (-8.75, 0) -> (-8.75, 3.75)
  line L25 (-5.25, 0) -> (-8.75, 0)
  line L26 (-5.25, 3.9571) -> (-5.25, 0)
  line L27 (-3.6893, 5.5178) -> (-5.25, 3.9571)
  line L28 (-3.3358, 5.1642) -> (-3.6893, 5.5178)
  line L29 (-4.75, 3.75) -> (-3.3358, 5.1642)
  line L30 (-4.75, 0) -> (-4.75, 3.75)
  line L31 (-1.25, 0) -> (-4.75, 0)
  line L32 (-1.25, 3.9571) -> (-1.25, 0)
  line L33 (0.3107, 5.5178) -> (-1.25, 3.9571)
  line L34 (0.6642, 5.1642) -> (0.3107, 5.5178)
  line L35 (-0.75, 3.75) -> (0.6642, 5.1642)
  line L36 (-0.75, 0) -> (-0.75, 3.75)
  line L37 (2.75, 0) -> (-0.75, 0)
  line L38 (2.75, 3.9571) -> (2.75, 0)
  line L39 (4.3107, 5.5178) -> (2.75, 3.9571)
  line L40 (4.6642, 5.1642) -> (4.3107, 5.5178)
  line L41 (3.25, 3.75) -> (4.6642, 5.1642)
  line L42 (3.25, 0) -> (3.25, 3.75)
  line L43 (6.75, 0) -> (3.25, 0)
  line L44 (6.75, 3.9571) -> (6.75, 0)
  line L45 (8.3107, 5.5178) -> (6.75, 3.9571)
  line L46 (8.6642, 5.1642) -> (8.3107, 5.5178)
  line L47 (7.25, 3.75) -> (8.6642, 5.1642)
  line L48 (7.25, 0) -> (7.25, 3.75)
  line L49 (10.75, 0) -> (7.25, 0)
  line L50 (10.75, 3.9571) -> (10.75, 0)
  line L51 (12.3107, 5.5178) -> (10.75, 3.9571)
  line L52 (12.6642, 5.1642) -> (12.3107, 5.5178)
  line L53 (11.25, 3.75) -> (12.6642, 5.1642)
  line L54 (11.25, 0) -> (11.25, 3.75)
  line L55 (14.75, 0) -> (11.25, 0)
  line L56 (14.75, 3.9571) -> (14.75, 0)
  line L57 (16.3107, 5.5178) -> (14.75, 3.9571)
  line L58 (16.6642, 5.1642) -> (16.3107, 5.5178)
  line L59 (15.25, 3.75) -> (16.6642, 5.1642)
  line L60 (15.25, 0) -> (15.25, 3.75)
  line L61 (18.75, 0) -> (15.25, 0)
  line L62 (18.75, 3.9571) -> (18.75, 0)
  line L63 (20.3107, 5.5178) -> (18.75, 3.9571)
  line L64 (20.6642, 5.1642) -> (20.3107, 5.5178)
  line L65 (19.25, 3.75) -> (20.6642, 5.1642)
  line L66 (19.25, 0) -> (19.25, 3.75)
  line L67 (22.75, 0) -> (19.25, 0)
  line L68 (22.75, 3.9571) -> (22.75, 0)
  line L69 (24.3107, 5.5178) -> (22.75, 3.9571)
  line L70 (24.6642, 5.1642) -> (24.3107, 5.5178)
  line L71 (23.25, 3.75) -> (24.6642, 5.1642)
  line L72 (23.25, 0) -> (23.25, 3.75)
  line L73 (27, 0) -> (23.25, 0)
  line L74 (27, 8.3107) -> (27, 0)
  curve K1
  curve K2
  curve K3
  curve K4
  curve K5
  curve K6
  curve K7
  curve K8
  curve K9
  curve K10
  curve K11
  curve K12
  curve K13
  curve K14
  curve K15
  curve K16
  curve K17
  curve K18
  curve K19
  curve K20
  line L75 (19.05, 24.3) -> (19.05, 26)
  line L76 (28.55, 20) -> (28.55, 25.1817)
  line L77 (22.05, 25.25) -> (22.05, 20)
  line L78 (16.05, 25.25) -> (22.05, 25.25)
  line L79 (16.05, 20) -> (16.05, 25.25)
  line L80 (10.55, 25.25) -> (10.55, 20)
  line L81 (4.55, 25.25) -> (10.55, 25.25)
  line L82 (4.55, 20) -> (4.55, 25.25)
  line L83 (0.05, 25.25) -> (0.05, 20)
  line L84 (-5.95, 25.25) -> (0.05, 25.25)
  line L85 (-5.95, 20) -> (-5.95, 25.25)
  line L86 (-9.95, 25.25) -> (-9.95, 20)
  line L87 (-15.95, 25.25) -> (-9.95, 25.25)
  line L88 (-15.95, 20) -> (-15.95, 25.25)
  line L89 (-19.45, 25.25) -> (-19.45, 20)
  line L90 (-24, 25.25) -> (-19.45, 25.25)
  line L91 (-26.25, 0) -> (-26.25, 23)
  line L92 (30.25, 8.3107) -> (27, 8.3107)
  line L93 (30.25, 23) -> (30.25, 8.3107)
  line L94 (15.3, 26) -> (22.8, 26)
  line L95 (22.8, 26) -> (22.8, 20)
  line L96 (15.3, 20) -> (15.3, 26)
  line L97 (11.3, 26) -> (11.3, 20)
  line L98 (0.8, 26) -> (0.8, 20)
  line L99 (-9.2, 26) -> (-9.2, 20)
  line L100 (-18.7, 26) -> (-18.7, 20)
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  point P78 (19.05, 24.3)
  point P77 (19.05, 26)
  midpoint P78 K8
  vertical L75
  vertical K7
  vertical K19
  collinear K8 K20
  vertical K3
  collinear K6 K18
  collinear K2 K6
  vertical K15
  collinear K4 K8
  collinear K8 K16
  collinear K6 K14
  vertical K11
  equal K12 K16
  collinear K12 K16
  collinear K10 K14
  equal K6 K18
  equal K2 K18
  equal K2 K14
  coincident P77 L94
  collinear K7 L95
  collinear K5 L96
  collinear K19 L97
  collinear K3 L98
  collinear K15 L99
  collinear K11 L100
  dimension "d216" distance P77 P78 = 1.7
  dimension "d211" Text1-Height = 4
  dimension "d212" Text2-Height = 4
  dimension "d213" Text3-Height = 4
  dimension "d214" Text4-Height = 4
  dimension "d215" Text5-Height = 4
  dimension "d217" distance = 10
sketch "Labels, Pockets (M5)" plane through (0, 0, 10) normal (0, 0, 1) x axis (-1, 0, 0)
  line L1 (20.8, 22.8777) -> (20.8, 24.3)
  line L2 (18.6704, 22.3292) -> (20.8, 22.8777)
  line L3 (20.8, 21.7846) -> (18.6704, 22.3292)
  line L4 (20.8, 20.3631) -> (20.8, 21.7846)
  line L5 (17.3, 20.3631) -> (20.8, 20.3631)
  line L6 (17.3, 21.2488) -> (17.3, 20.3631)
  line L7 (19.9692, 21.2488) -> (17.3, 21.2488)
  line L8 (17.3, 21.9313) -> (19.9692, 21.2488)
  line L9 (17.3, 22.7331) -> (17.3, 21.9313)
  line L10 (19.9692, 23.4143) -> (17.3, 22.7331)
  line L11 (17.3, 23.4143) -> (19.9692, 23.4143)
  line L12 (17.3, 24.3) -> (17.3, 23.4143)
  line L13 (20.8, 24.3) -> (17.3, 24.3)
  line L14 (20.8, 17.1281) -> (20.8, 19.4368)
  line L15 (20.0241, 17.1281) -> (20.8, 17.1281)
  line L16 (20.0241, 18.6919) -> (20.0241, 17.1281)
  line L17 (19.4988, 18.7754) -> (20.0241, 18.6919)
  curve K1 (19.6134, 18.4543) -> (19.4988, 18.7754)
  curve K2 (19.6516, 18.1404) -> (19.6134, 18.4543)
  curve K3 (19.3341, 17.2881) -> (19.6516, 18.1404)
  curve K4 (18.5343, 16.961) -> (19.3341, 17.2881)
  curve K5 (17.8825, 17.1293) -> (18.5343, 16.961)
  curve K6 (17.405, 17.6068) -> (17.8825, 17.1293)
  curve K7 (17.2403, 18.3982) -> (17.405, 17.6068)
  curve K8 (17.306, 18.9915) -> (17.2403, 18.3982)
  curve K9 (17.5017, 19.4117) -> (17.306, 18.9915)
  curve K10 (17.7966, 19.6922) -> (17.5017, 19.4117)
  curve K11 (18.2072, 19.8713) -> (17.7966, 19.6922)
  line L18 (18.3147, 18.8877) -> (18.2072, 19.8713)
  curve K12 (17.9554, 18.7205) -> (18.3147, 18.8877)
  curve K13 (17.8324, 18.4078) -> (17.9554, 18.7205)
  curve K14 (17.9864, 18.0723) -> (17.8324, 18.4078)
  curve K15 (18.446, 17.9398) -> (17.9864, 18.0723)
  curve K16 (18.9044, 18.0735) -> (18.446, 17.9398)
  curve K17 (19.05, 18.4293) -> (18.9044, 18.0735)
  curve K18 (18.9808, 18.7014) -> (19.05, 18.4293)
  curve K19 (18.7993, 18.9163) -> (18.9808, 18.7014)
  line L19 (18.9187, 19.7447) -> (18.7993, 18.9163)
  line L20 (20.8, 19.4368) -> (18.9187, 19.7447)
  line L21 (9.3, 22.8777) -> (9.3, 24.3)
  line L22 (7.1704, 22.3292) -> (9.3, 22.8777)
  line L23 (9.3, 21.7846) -> (7.1704, 22.3292)
  line L24 (9.3, 20.3631) -> (9.3, 21.7846)
  line L25 (5.8, 20.3631) -> (9.3, 20.3631)
  line L26 (5.8, 21.2488) -> (5.8, 20.3631)
  line L27 (8.4692, 21.2488) -> (5.8, 21.2488)
  line L28 (5.8, 21.9313) -> (8.4692, 21.2488)
  line L29 (5.8, 22.7331) -> (5.8, 21.9313)
  line L30 (8.4692, 23.4143) -> (5.8, 22.7331)
  line L31 (5.8, 23.4143) -> (8.4692, 23.4143)
  line L32 (5.8, 24.3) -> (5.8, 23.4143)
  line L33 (9.3, 24.3) -> (5.8, 24.3)
  line L34 (6.4542, 19.931) -> (6.4542, 18.1595)
  line L35 (7.254, 19.931) -> (6.4542, 19.931)
  line L36 (9.3597, 18.1595) -> (7.254, 19.931)
  line L37 (9.3597, 17.3119) -> (9.3597, 18.1595)
  line L38 (7.2086, 17.3119) -> (9.3597, 17.3119)
  line L39 (7.2086, 16.8726) -> (7.2086, 17.3119)
  line L40 (6.4542, 16.8726) -> (7.2086, 16.8726)
  line L41 (6.4542, 17.3119) -> (6.4542, 16.8726)
  line L42 (5.8, 17.3119) -> (6.4542, 17.3119)
  line L43 (5.8, 18.1595) -> (5.8, 17.3119)
  line L44 (6.4542, 18.1595) -> (5.8, 18.1595)
  line L45 (8.3101, 18.1595) -> (7.2086, 18.1595)
  line L46 (7.2086, 19.0955) -> (8.3101, 18.1595)
  line L47 (7.2086, 18.1595) -> (7.2086, 19.0955)
  line L48 (-1.2, 22.8777) -> (-1.2, 24.3)
  line L49 (-3.3296, 22.3292) -> (-1.2, 22.8777)
  line L50 (-1.2, 21.7846) -> (-3.3296, 22.3292)
  line L51 (-1.2, 20.3631) -> (-1.2, 21.7846)
  line L52 (-4.7, 20.3631) -> (-1.2, 20.3631)
  line L53 (-4.7, 21.2488) -> (-4.7, 20.3631)
  line L54 (-2.0308, 21.2488) -> (-4.7, 21.2488)
  line L55 (-4.7, 21.9313) -> (-2.0308, 21.2488)
  line L56 (-4.7, 22.7331) -> (-4.7, 21.9313)
  line L57 (-2.0308, 23.4143) -> (-4.7, 22.7331)
  line L58 (-4.7, 23.4143) -> (-2.0308, 23.4143)
  line L59 (-4.7, 24.3) -> (-4.7, 23.4143)
  line L60 (-1.2, 24.3) -> (-4.7, 24.3)
  line L61 (-2.0475, 19.8068) -> (-2.2123, 18.8877)
  curve K20 (-1.3743, 19.3663) -> (-2.0475, 19.8068)
  curve K21 (-1.1403, 18.4436) -> (-1.3743, 19.3663)
  curve K22 (-1.3958, 17.4528) -> (-1.1403, 18.4436)
  curve K23 (-2.038, 17.1472) -> (-1.3958, 17.4528)
  curve K24 (-2.4486, 17.2714) -> (-2.038, 17.1472)
  curve K25 (-2.7709, 17.6462) -> (-2.4486, 17.2714)
  curve K26 (-2.8879, 17.3358) -> (-2.7709, 17.6462)
  curve K27 (-3.1708, 17.0648) -> (-2.8879, 17.3358)
  curve K28 (-3.5898, 16.9681) -> (-3.1708, 17.0648)
  curve K29 (-4.176, 17.1281) -> (-3.5898, 16.9681)
  curve K30 (-4.6081, 17.5889) -> (-4.176, 17.1281)
  curve K31 (-4.7597, 18.3791) -> (-4.6081, 17.5889)
  curve K32 (-4.6475, 19.1324) -> (-4.7597, 18.3791)
  curve K33 (-4.3192, 19.586) -> (-4.6475, 19.1324)
  curve K34 (-3.7761, 19.8593) -> (-4.3192, 19.586)
  line L62 (-3.6471, 18.8877) -> (-3.7761, 19.8593)
  curve K35 (-4.0542, 18.7098) -> (-3.6471, 18.8877)
  curve K36 (-4.1676, 18.403) -> (-4.0542, 18.7098)
  curve K37 (-4.0244, 18.0771) -> (-4.1676, 18.403)
  curve K38 (-3.6424, 17.947) -> (-4.0244, 18.0771)
  curve K39 (-3.2651, 18.0723) -> (-3.6424, 17.947)
  curve K40 (-3.1314, 18.4126) -> (-3.2651, 18.0723)
  curve K41 (-3.1887, 18.7277) -> (-3.1314, 18.4126)
  line L63 (-2.494, 18.6776) -> (-3.1887, 18.7277)
  curve K42 (-2.5059, 18.551) -> (-2.494, 18.6776)
  curve K43 (-2.3842, 18.2323) -> (-2.5059, 18.551)
  curve K44 (-2.0953, 18.1046) -> (-2.3842, 18.2323)
  curve K45 (-1.8398, 18.2001) -> (-2.0953, 18.1046)
  curve K46 (-1.7443, 18.4627) -> (-1.8398, 18.2001)
  curve K47 (-1.8482, 18.742) -> (-1.7443, 18.4627)
  curve K48 (-2.2123, 18.8877) -> (-1.8482, 18.742)
  line L64 (-14.7, 24.3) -> (-14.7, 21.3825)
  curve K49 (-13.8871, 23.9956) -> (-14.7, 24.3)
  curve K50 (-12.9882, 23.0418) -> (-13.8871, 23.9956)
  curve K51 (-12.5059, 22.4951) -> (-12.9882, 23.0418)
  curve K52 (-12.1932, 22.3757) -> (-12.5059, 22.4951)
  curve K53 (-11.9198, 22.4939) -> (-12.1932, 22.3757)
  curve K54 (-11.8064, 22.7911) -> (-11.9198, 22.4939)
  curve K55 (-11.9234, 23.0955) -> (-11.8064, 22.7911)
  curve K56 (-12.3364, 23.2543) -> (-11.9234, 23.0955)
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sketch "Labels, Pockets (M5, 4mm)" plane through (0, 0, 10) normal (0, 0, 1) x axis (-1, 0, 0)
  line L1 (28.55, 20) -> (28.55, 25.1817)
  line L2 (22.05, 25.25) -> (22.05, 20)
  line L3 (16.05, 25.25) -> (22.05, 25.25)
  line L4 (16.05, 20) -> (16.05, 25.25)
  line L5 (10.55, 25.25) -> (10.55, 20)
  line L6 (4.55, 25.25) -> (10.55, 25.25)
  line L7 (4.55, 20) -> (4.55, 25.25)
  line L8 (0.05, 25.25) -> (0.05, 20)
  line L9 (-5.95, 25.25) -> (0.05, 25.25)
  line L10 (-5.95, 20) -> (-5.95, 25.25)
  line L11 (-9.95, 25.25) -> (-9.95, 20)
  line L12 (-15.95, 25.25) -> (-9.95, 25.25)
  line L13 (-15.95, 20) -> (-15.95, 25.25)
  line L14 (-19.45, 25.25) -> (-19.45, 20)
  line L15 (-24, 25.25) -> (-19.45, 25.25)
  line L16 (-26.25, 0) -> (-26.25, 23)
  line L17 (-21.25, 0) -> (-26.25, 0)
  line L18 (-21.25, 3.9571) -> (-21.25, 0)
  line L19 (-19.6893, 5.5178) -> (-21.25, 3.9571)
  line L20 (-19.3358, 5.1642) -> (-19.6893, 5.5178)
  line L21 (-20.75, 3.75) -> (-19.3358, 5.1642)
  line L22 (-20.75, 0) -> (-20.75, 3.75)
  line L23 (-17.25, 0) -> (-20.75, 0)
  line L24 (-17.25, 3.9571) -> (-17.25, 0)
  line L25 (-15.6893, 5.5178) -> (-17.25, 3.9571)
  line L26 (-15.3358, 5.1642) -> (-15.6893, 5.5178)
  line L27 (-16.75, 3.75) -> (-15.3358, 5.1642)
  line L28 (-16.75, 0) -> (-16.75, 3.75)
  line L29 (-13.25, 0) -> (-16.75, 0)
  line L30 (-13.25, 3.9571) -> (-13.25, 0)
  line L31 (-11.6893, 5.5178) -> (-13.25, 3.9571)
  line L32 (-11.3358, 5.1642) -> (-11.6893, 5.5178)
  line L33 (-12.75, 3.75) -> (-11.3358, 5.1642)
  line L34 (-12.75, 0) -> (-12.75, 3.75)
  line L35 (-9.25, 0) -> (-12.75, 0)
  line L36 (-9.25, 3.9571) -> (-9.25, 0)
  line L37 (-7.6893, 5.5178) -> (-9.25, 3.9571)
  line L38 (-7.3358, 5.1642) -> (-7.6893, 5.5178)
  line L39 (-8.75, 3.75) -> (-7.3358, 5.1642)
  line L40 (-8.75, 0) -> (-8.75, 3.75)
  line L41 (-5.25, 0) -> (-8.75, 0)
  line L42 (-5.25, 3.9571) -> (-5.25, 0)
  line L43 (-3.6893, 5.5178) -> (-5.25, 3.9571)
  line L44 (-3.3358, 5.1642) -> (-3.6893, 5.5178)
  line L45 (-4.75, 3.75) -> (-3.3358, 5.1642)
  line L46 (-4.75, 0) -> (-4.75, 3.75)
  line L47 (-1.25, 0) -> (-4.75, 0)
  line L48 (-1.25, 3.9571) -> (-1.25, 0)
  line L49 (0.3107, 5.5178) -> (-1.25, 3.9571)
  line L50 (0.6642, 5.1642) -> (0.3107, 5.5178)
  line L51 (-0.75, 3.75) -> (0.6642, 5.1642)
  line L52 (-0.75, 0) -> (-0.75, 3.75)
  line L53 (2.75, 0) -> (-0.75, 0)
  line L54 (2.75, 3.9571) -> (2.75, 0)
  line L55 (4.3107, 5.5178) -> (2.75, 3.9571)
  line L56 (4.6642, 5.1642) -> (4.3107, 5.5178)
  line L57 (3.25, 3.75) -> (4.6642, 5.1642)
  line L58 (3.25, 0) -> (3.25, 3.75)
  line L59 (6.75, 0) -> (3.25, 0)
  line L60 (6.75, 3.9571) -> (6.75, 0)
  line L61 (8.3107, 5.5178) -> (6.75, 3.9571)
  line L62 (8.6642, 5.1642) -> (8.3107, 5.5178)
  line L63 (7.25, 3.75) -> (8.6642, 5.1642)
  line L64 (7.25, 0) -> (7.25, 3.75)
  line L65 (10.75, 0) -> (7.25, 0)
  line L66 (10.75, 3.9571) -> (10.75, 0)
  line L67 (12.3107, 5.5178) -> (10.75, 3.9571)
  line L68 (12.6642, 5.1642) -> (12.3107, 5.5178)
  line L69 (11.25, 3.75) -> (12.6642, 5.1642)
  line L70 (11.25, 0) -> (11.25, 3.75)
  line L71 (14.75, 0) -> (11.25, 0)
  line L72 (14.75, 3.9571) -> (14.75, 0)
  line L73 (16.3107, 5.5178) -> (14.75, 3.9571)
  line L74 (16.6642, 5.1642) -> (16.3107, 5.5178)
  line L75 (15.25, 3.75) -> (16.6642, 5.1642)
  line L76 (15.25, 0) -> (15.25, 3.75)
  line L77 (18.75, 0) -> (15.25, 0)
  line L78 (18.75, 3.9571) -> (18.75, 0)
  line L79 (20.3107, 5.5178) -> (18.75, 3.9571)
  line L80 (20.6642, 5.1642) -> (20.3107, 5.5178)
  line L81 (19.25, 3.75) -> (20.6642, 5.1642)
  line L82 (19.25, 0) -> (19.25, 3.75)
  line L83 (22.75, 0) -> (19.25, 0)
  line L84 (22.75, 3.9571) -> (22.75, 0)
  line L85 (24.3107, 5.5178) -> (22.75, 3.9571)
  line L86 (24.6642, 5.1642) -> (24.3107, 5.5178)
  line L87 (23.25, 3.75) -> (24.6642, 5.1642)
  line L88 (23.25, 0) -> (23.25, 3.75)
  line L89 (27, 0) -> (23.25, 0)
  line L90 (27, 8.3107) -> (27, 0)
  line L91 (30.25, 8.3107) -> (27, 8.3107)
  line L92 (30.25, 23) -> (30.25, 8.3107)
  line L93 (21.05, 22.6745) -> (21.05, 24.3)
  line L94 (18.6162, 22.0476) -> (21.05, 22.6745)
  line L95 (21.05, 21.4252) -> (18.6162, 22.0476)
  line L96 (21.05, 19.8007) -> (21.05, 21.4252)
  line L97 (17.05, 19.8007) -> (21.05, 19.8007)
  line L98 (17.05, 20.813) -> (17.05, 19.8007)
  line L99 (20.1005, 20.813) -> (17.05, 20.813)
  line L100 (17.05, 21.5929) -> (20.1005, 20.813)
  line L101 (17.05, 22.5092) -> (17.05, 21.5929)
  line L102 (20.1005, 23.2877) -> (17.05, 22.5092)
  line L103 (17.05, 23.2877) -> (20.1005, 23.2877)
  line L104 (17.05, 24.3) -> (17.05, 23.2877)
  line L105 (21.05, 24.3) -> (17.05, 24.3)
  line L106 (21.05, 16.1035) -> (21.05, 18.742)
  line L107 (20.1632, 16.1035) -> (21.05, 16.1035)
  line L108 (20.1632, 17.8907) -> (20.1632, 16.1035)
  line L109 (19.563, 17.9862) -> (20.1632, 17.8907)
  curve K1 (19.6939, 17.6192) -> (19.563, 17.9862)
  curve K2 (19.7376, 17.2604) -> (19.6939, 17.6192)
  curve K3 (19.3747, 16.2864) -> (19.7376, 17.2604)
  curve K4 (18.4606, 15.9126) -> (19.3747, 16.2864)
  curve K5 (17.7158, 16.1049) -> (18.4606, 15.9126)
  curve K6 (17.1701, 16.6506) -> (17.7158, 16.1049)
  curve K7 (16.9818, 17.5551) -> (17.1701, 16.6506)
  curve K8 (17.0568, 18.2332) -> (16.9818, 17.5551)
  curve K9 (17.2806, 18.7134) -> (17.0568, 18.2332)
  curve K10 (17.6175, 19.034) -> (17.2806, 18.7134)
  curve K11 (18.0868, 19.2386) -> (17.6175, 19.034)
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sketch "Labels, Lines (50mm, Original)" plane through (0, 0, 0) normal (0, 0, 1) x axis (1, 0, 0)
  dimension "d227" = 3.5
  dimension "d228" = 3.5
  dimension "d229" = 3.5
  dimension "d230" = 3.5
  dimension "d231" = 3.5
  dimension "d232" = 3.5
  dimension "d233" = 3.5
  dimension "d234" = 3.5
  dimension "d235" = 3.5
  dimension "d236" = 3.5
  dimension "d237" = 3.5
  dimension "d238" = 3.5
  dimension "d239" = 3.5
  dimension "d240" = 3.5
  dimension "d241" = 3.5
  dimension "d242" = 3.5
  dimension "d243" = 3.5
  dimension "d244" = 3.5
  dimension "d245" = 3.5
  dimension "d246" = 3.5
  dimension "d247" = 3.5
  dimension "d248" = 3.5
  dimension "d249" = 3.5
  dimension "d250" = 3.5
  dimension "d253" = 4
  dimension "d254" = 0
  dimension "d255" = 6.5
  dimension "d256" = 3.75
  dimension "d258" = 2.33
  dimension "d259" = 1.9
  dimension "d260" = 0.4707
